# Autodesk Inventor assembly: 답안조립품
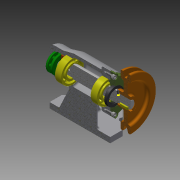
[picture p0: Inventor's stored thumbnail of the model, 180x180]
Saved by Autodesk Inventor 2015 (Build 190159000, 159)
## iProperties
Created: 2019-12
Part Number: 답안조립품
Document SubType Name: Assembly
Designer: 1010101
Author: 1010101
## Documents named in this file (12)
- C:\Users\1010101\Desktop\새 폴더\491204V1043\답안조립품.iam
- C:\Users\1010101\Desktop\491204V1043\V벨트풀리.ipt
- C:\Users\1010101\Desktop\491204V1043\멈춤나사 M3.ipt
- C:\Users\1010101\Desktop\491204V1043\베어링 6004.ipt
- C:\Users\1010101\Desktop\491204V1043\베어링 51202.ipt
- C:\Users\1010101\Desktop\491204V1043\본체.ipt
- C:\Users\1010101\Desktop\491204V1043\볼트 M4.ipt
- C:\Users\1010101\Desktop\491204V1043\어댑터슬리브.ipt
- C:\Users\1010101\Desktop\491204V1043\오일 실.ipt
- C:\Users\1010101\Desktop\491204V1043\축.ipt
- C:\Users\1010101\Desktop\491204V1043\커버.ipt
- C:\Users\1010101\Desktop\491204V1043\키 5 x 5 x 16.ipt
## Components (1 placed, 1 different names)
1. V벨트풀리:1 — 각도:2
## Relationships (1: Angle 1)
- 각도:2 [Angle]: V벨트풀리:1
